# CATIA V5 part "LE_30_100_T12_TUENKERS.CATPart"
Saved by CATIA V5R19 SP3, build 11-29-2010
Part number: LE_30_100_T12_TUENKERS
Material "MISCHDICHTE": density 3333 kg/m3, Young's modulus 2e+11 Pa, Poisson ratio 0.266
Bounding box of the stored display mesh (mm): x -275 to 200, y -122 to 122, z 0 to 130.5
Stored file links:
  G:\Konstruktion\Modelle\Catia_V5\LE_30_100_T12_TUENKERS.CATPart
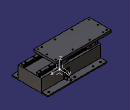
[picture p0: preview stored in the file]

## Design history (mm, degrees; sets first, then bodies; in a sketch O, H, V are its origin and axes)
AxisSystem1: origin (0, 0, 0), X (1, 0, 0), Y (0, 1, 0), Z (0, 0, 1)
Body1 "LE_30_100_T12_TUENKERS" (main body)
  Body2 "GRUNDKOERPER_LE_30_100.1\\PartBody"
    Solid1: solid without history
  Assemble1: tool Body2
  Body3 "PLATTE_LE_30_100.1\\PartBody"
    Solid2 "Solid.1": solid without history
    Sketch1 on face of Solid2, origin (0, 0, 130.5), H (1, 0, 0), V (0, 1, 0)
      construction line L1 (-235, 60) -> (60, 60)
      construction line L2 (60, 60) -> (60, -60)
      construction line L3 (60, -60) -> (-235, -60)
      construction line L4 (-235, -60) -> (-235, 60)
      point P5 (-145, 60)
      point P6 (-30, -60)
      reference projected circle E1 centre (-30, -60) radius 4.188 from edge [face of Solid2 | face of Solid2]
      reference projected circle E2 centre (-145, 60) radius 4.188 from edge [face of Solid2 | face of Solid2]
      point P7 (-235, -64)
      circle A1 centre (60, -60) radius 4
      circle A2 centre (-235, 60) radius 4
      distance L4 P5 = 90
      distance L2 P6 = 90
      radius A2 = 4
      radius A1 = 4
      horizontal: L1 H, L3 H
      vertical: L2 V, L4 V
      concentricity: P6 E1, E2 P5
      coincidence: L1 P5, L3 P6, P7 L4
    Pocket1: profile Sketch1, direction (0, 0, -1), up to face of Solid2
  Assemble2: tool Body3
  Body4 "1666-8XX-2X.1\\MANIFOLD_SOLID_BREP #6388"
    Solid3 "Solid.1": solid without history
  Assemble3: tool Body4
  Body5 "FUEHRUNGSSCHIENE_LE_30_100.1\\Volumenkörper1"
    Solid4 "Solid.1": solid without history
  Assemble4: tool Body5
  Body6 "1666-8XX-2X.2\\MANIFOLD_SOLID_BREP #6388"
    Solid5 "Solid.1": solid without history
  Assemble5: tool Body6
  Body7 "FUEHRUNGSSCHIENE_LE_30_100.2\\Volumenkörper1"
    Solid6 "Solid.1": solid without history
  Assemble6: tool Body7
  Body8 "1666-8XX-2X.3\\MANIFOLD_SOLID_BREP #6388"
    Solid7 "Solid.1": solid without history
  Assemble7: tool Body8
  Body9 "1666-8XX-2X.4\\MANIFOLD_SOLID_BREP #6388"
    Solid8 "Solid.1": solid without history
  Assemble8: tool Body9
  Body10 "ABFRAGE_T12.1\\PartBody"
    Solid9 "Solid.1": solid without history
  Assemble9: tool Body10
  Body11 "ZYLINDERSCHRAUBE_M5X25_DIN_912.1\\PartBody"
    Solid10 "Solid.1": solid without history
  Assemble10: tool Body11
